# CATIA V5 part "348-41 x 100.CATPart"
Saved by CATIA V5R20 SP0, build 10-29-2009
Part number: 348-41 x 100
Definition: NONE
Nomenclature: 348-41 x 100
Source: Unknown
Description: 348-41 x 100
Bounding box of the stored display mesh (mm): x 0 to 100, y -27.5 to 27.5, z -27.5 to 27.5
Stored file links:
  C:\Users\Utente\Desktop\IO LAVORO\3D X SITO CF\X SITO\3D files 348\348-41 x 100.CATPart
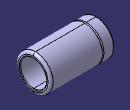
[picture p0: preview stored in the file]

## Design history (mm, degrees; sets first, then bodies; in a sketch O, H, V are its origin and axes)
Body1 "348-41 x 100" (main body)
  Solid1: solid without history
